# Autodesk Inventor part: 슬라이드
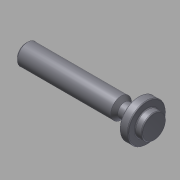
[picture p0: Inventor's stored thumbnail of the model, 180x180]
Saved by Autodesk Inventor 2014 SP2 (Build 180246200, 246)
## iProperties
Company: 한국ATC센터
Created: 2015-12
Part Number: 슬라이드
Document SubType Name: Modeling
Designer: mdu
Density: 7.86 g/cm^3
Mass: 72.8967 g
Surface Area: 36.3054 cm^2
Volume: 9.27439 cm^3
Material: 강철, 연강
Appearance: 강철
Author: mdu
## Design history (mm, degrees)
sketch "스케치1"
  geometry: L1 (-35, 0)-(35, 0); L2 (35, 0)-(35, 11); L3 (35, 11)-(30, 11); L4 (30, 11)-(30, 4); L5 (30, 4)-(22, 4); L6 (22, 4)-(20, 6); L7 (20, 6)-(-35, 6); L8 (-35, 6)-(-35, 0); 1 further point
  constraints: 16 end point, 4 parallel, 2 midpoint, 2 perpendicular, 1 horizontal
  dimensions: "d0" = 70 distance of L1.start L1.end; "d1" = 12 diameter of L7 L1; "d2" = 22 diameter of L3 L1; "d3" = 5 distance of L2.end L3.end; "d4" = 8 diameter of L5 L1; "d5" = 135 deg angle of L6 L5; "d6" = 15 distance from line of L2 L6.end
revolve "회전1" sketch "스케치1" stored, may be unused: angle "d7" = 90 deg
chamfer "모따기1" distance "d8" = 1; stored, may be unused: second distance "d9" = 2, angle "d10" = 45 deg
fillet "모깎기1" dims "d11" = 0.5
sketch "스케치5"
  geometry: C1 r 7 at (0, 0); 1 further point
  constraints: 1 centre point, 1 coincident
  dimensions: "d23" = 14 diameter of C1
extrude "돌출2" join sketch "스케치5" distance "d24" = 4; taper "d25" = 0 deg
fillet "모깎기3" dims "d26" = 0.5
node "솔리드1"
